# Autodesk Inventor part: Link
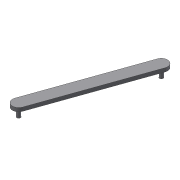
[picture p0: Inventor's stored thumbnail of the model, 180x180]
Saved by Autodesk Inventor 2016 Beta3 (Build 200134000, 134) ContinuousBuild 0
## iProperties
Created: 2016-03
Part Number: Link
Material: Generic
Document SubType Name: Modeling
Designer: Gaurav
Density: 1 g/cm^3
Appearance: Default
Author: Gaurav
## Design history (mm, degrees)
sketch "Sketch1"
  geometry: C1 r 2 at (10, 0) reference; C2 r 2 at (-20.493, -86.321) reference; 1 further point
  node "Reference1"
  node "Reference2"
workplane "Work Plane1"
extrude "Extrusion1" new body sketch "Sketch1" stored distance "d0" = 10; taper "d1" = 0 deg
sketch "Sketch2"
  geometry: L1 (-35.208, -84.656)-(-4.714, 1.665); L2 (-25.779, -87.987)-(4.714, -1.665); C1 r 2 at (-30.493, -86.321); C2 r 2 at (0, 0); C3 r 2 at (-30.493, -86.321) reference; C4 r 2 at (0, 0) reference; A1 r 5 centre (-30.493, -86.321) between (-35.208, -84.656) and (-25.779, -87.987); A2 r 5 centre (0, 0) between (4.714, -1.665) and (-4.714, 1.665); 2 further points
  constraints: 4 centre point, 4 concentric, 4 end point, 4 point on circle, 4 tangent, 1 coincident
  dimensions: "d3" = 10 diameter of A2
extrude "Extrusion2" join sketch "Sketch2" distance "d4" = 3; taper "d5" = 0 deg
body "Solid1"
